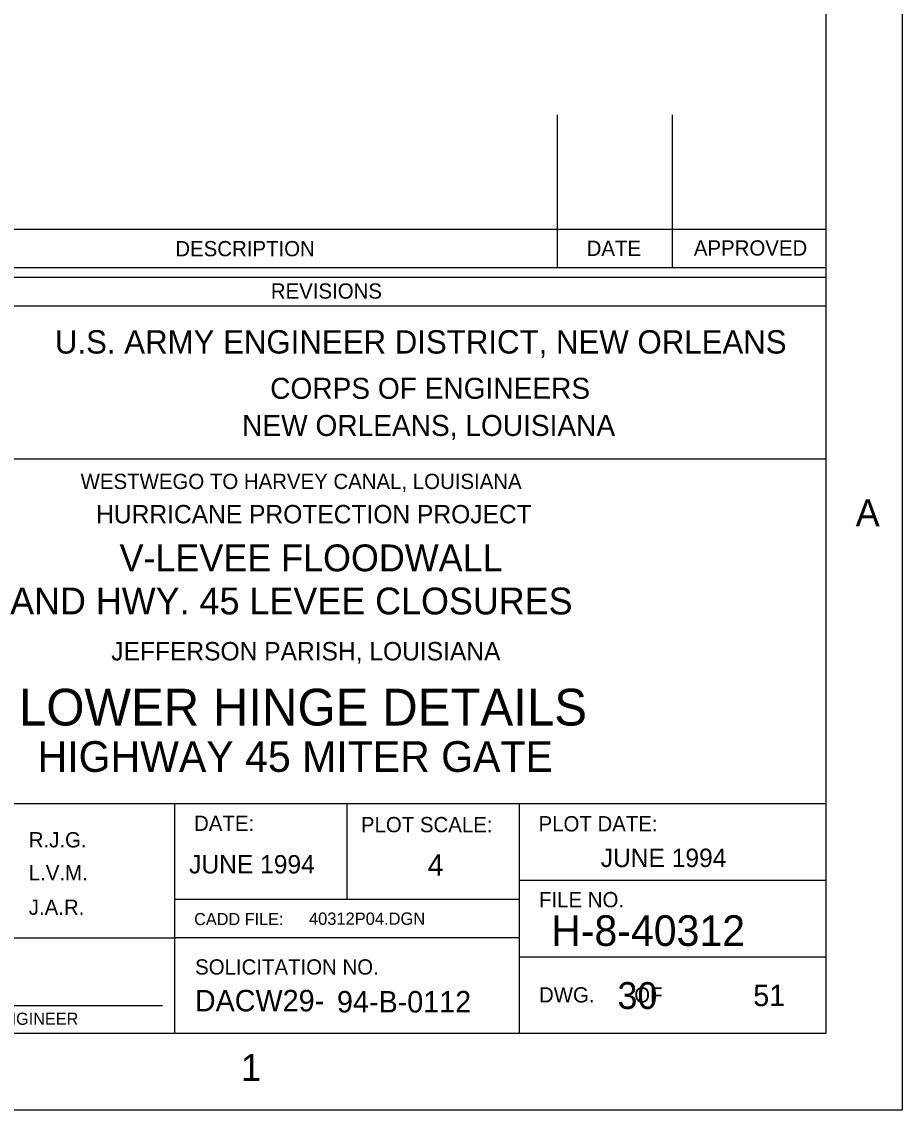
# Model space of a CAD drawing. Extents: x -0.2 to 13.5, y -0.2 to 9.5.
# Drawn here: x 11.417 to 13.333, y 0 to 2.369 of the extents above; entities that cross this region are included whole.
import ezdxf

# ---------------------------------------------------------------- set-up
doc = ezdxf.new("R2010")
doc.units = 0
doc.layers.add('Level 1', color=7, linetype='Continuous')
doc.layers.add('Level 2', color=7, linetype='Continuous')

msp = doc.modelspace()

# ---------------------------------------------------------------- linework, layer by layer
at = {"layer": 'Level 1'}
for p, q in [((12.5833, 1.8333), (12.5833, 2.1667)), ((12.8333, 1.8333), (12.8333, 2.1667)), ((13.1667, 1.9167), (11, 1.9167)), ((13.1667, 1.8333), (11, 1.8333)), ((13.1667, 1.8125), (11, 1.8125)), ((13.1667, 1.75), (11, 1.75)), ((13.1667, 1.4167), (11, 1.4167)), ((13.1667, 0.6667), (11, 0.6667)), ((11.75, 0.1667), (11.75, 0.6667)), ((12.125, 0.4583), (12.125, 0.6667)), ((12.5, 0.1667), (12.5, 0.6667)), ((13.1667, 0.5), (12.5, 0.5)), ((12.5, 0.4583), (11.75, 0.4583)), ((11, 0.375), (11.75, 0.375)), ((12.5, 0.375), (11.75, 0.375)), ((13.1667, 0.3333), (12.5, 0.3333)), ((11.0224, 0.2278), (11.7234, 0.2278))]:
    msp.add_line(p, q, dxfattribs=at)
for points in [[(0, 9.3333), (13.3333, 9.3333), (13.3333, 0), (0, 0)], [(0.5, 9.1667), (13.1667, 9.1667), (13.1667, 0.1667), (0.5, 0.1667)]]:
    msp.add_lwpolyline(points, close=True, dxfattribs=at)

# ---------------------------------------------------------------- texts
for s, height, p in [('DESCRIPTION', 0.033208, (11.7513, 1.8585)), ('DATE', 0.03321, (12.6465, 1.8593)), ('APPROVED', 0.03321, (12.8798, 1.86)), ('REVISIONS', 0.03321, (11.9591, 1.7663)), ('U.S. ARMY ENGINEER DISTRICT, NEW ORLEANS', 0.050792, (11.4891, 1.6468)), ('CORPS OF ENGINEERS', 0.045713, (11.9577, 1.5483)), ('NEW ORLEANS, LOUISIANA', 0.045713, (11.8967, 1.4675)), ('A', 0.0584, (13.2321, 1.2711)), ('DATE:', 0.03321, (11.792, 0.6079)), ('PLOT DATE:', 0.03321, (12.5418, 0.6069)), ('PLOT SCALE:', 0.033208, (12.1552, 0.605)), ('FILE NO.', 0.03321, (12.5428, 0.4417)), ('CADD FILE:', 0.02642, (11.7923, 0.4028)), ('SOLICITATION NO.', 0.033208, (11.7943, 0.2952)), ('DACW29-', 0.04679, (11.7937, 0.2152)), ('DWG.       OF', 0.033208, (12.5428, 0.2345)), ('DESIGN ENGINEER', 0.026417, (11.2103, 0.1859)), ('1', 0.0584, (11.8942, 0.0637))]:
    msp.add_text(s, height=height, dxfattribs=at).set_placement(p)
at = {"layer": 'Level 2'}
for s, height, p in [('WESTWEGO TO HARVEY CANAL, LOUISIANA', 0.033208, (11.5452, 1.352)), ('HURRICANE PROTECTION PROJECT', 0.04, (11.5789, 1.2773)), ('V-LEVEE FLOODWALL', 0.058417, (11.6299, 1.1729)), ('AND HWY. 45 LEVEE CLOSURES', 0.058417, (11.3917, 1.0791)), ('JEFFERSON PARISH, LOUISIANA', 0.04, (11.6118, 0.979)), ('LOWER HINGE DETAILS', 0.08, (11.4109, 0.8373)), ('HIGHWAY 45 MITER GATE', 0.066792, (11.4515, 0.7364)), ('R.J.G.', 0.03321, (11.4323, 0.572)), ('JUNE 1994', 0.04, (12.6771, 0.5293)), ('JUNE 1994', 0.04, (11.7812, 0.5153)), ('4', 0.0468, (12.3004, 0.5104)), ('L.V.M.', 0.03321, (11.4323, 0.5002)), ('J.A.R.', 0.03321, (11.4323, 0.4252)), ('40312P04.DGN', 0.026792, (12.0421, 0.4035)), ('H-8-40312', 0.06679, (12.5692, 0.3575)), ('30', 0.05842, (12.7136, 0.2204)), ('51', 0.04679, (13.0091, 0.2265)), ('94-B-0112', 0.04679, (12.103, 0.2127))]:
    msp.add_text(s, height=height, dxfattribs=at).set_placement(p)

doc.saveas('drawing.dxf')
